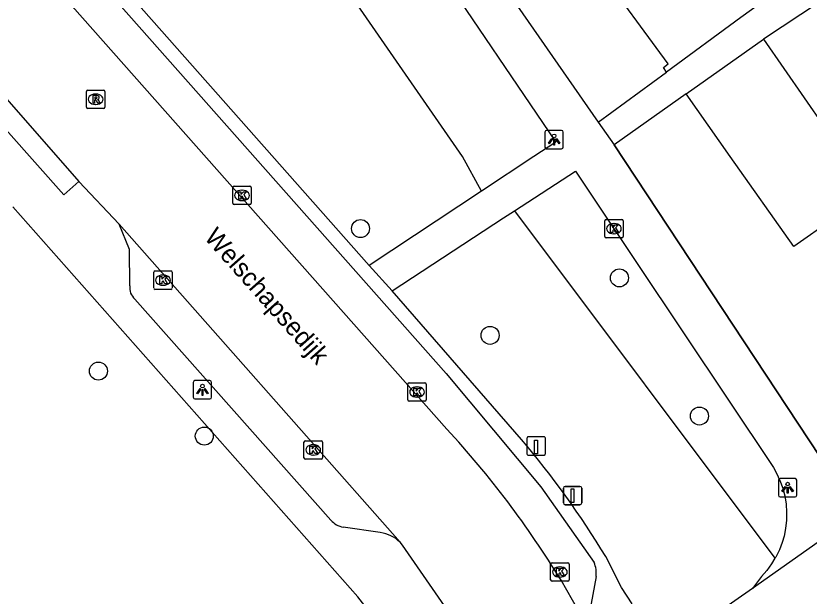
# Model space of a CAD drawing. Extents: x 157466 to 158888, y 383063 to 384677.
# Drawn here: x 157968.71 to 158011.77, y 383476.12 to 383507.63 of the extents above; entities that cross this region are included whole.
import ezdxf

# ---------------------------------------------------------------- set-up
doc = ezdxf.new("R2010")
doc.units = 0
for name, color, linetype in [('IMGEO_Boom', 7, 'Continuous'), ('IMGEO_Groenvoorziening', 7, 'Continuous'), ('IMGEO_Kolk', 7, 'Continuous'), ('IMGEO_Laadpaal', 7, 'Continuous'), ('IMGEO_Lichtpunt', 7, 'Continuous'), ('IMGEO_Muur', 7, 'Continuous'), ('IMGEO_Openbare_ruimte_label', 7, 'Continuous'), ('IMGEO_Pand', 7, 'Continuous'), ('IMGEO_Rijbaan_lokaal_gesloten', 7, 'Continuous'), ('IMGEO_Rioolput', 7, 'Continuous'), ('IMGEO_Verkeersbordpaal', 7, 'Continuous'), ('IMGEO_Voetpad_open', 7, 'Continuous')]:
    doc.layers.add(name, color=color, linetype=linetype)

msp = doc.modelspace()

# ---------------------------------------------------------------- linework, layer by layer
at = {"layer": 'IMGEO_Boom'}
for centre in [(157987.417, 383496.084), (158001.474, 383493.406), (157994.451, 383490.283), (157973.188, 383488.344), (158005.819, 383485.903), (157978.938, 383484.812)]:
    msp.add_circle(centre, 0.489, dxfattribs=at)
at = {"layer": 'IMGEO_Groenvoorziening'}
for points in [[(157993.986, 383498.111), (157992.947, 383500), (157978.989, 383520.199)], [(157995.779, 383497.049), (158009.92, 383478.175)]]:
    msp.add_lwpolyline(points, dxfattribs=at)
at = {"layer": 'IMGEO_Kolk'}
for p, q in [((157980.558, 383498.383), (157981.41, 383498.383)), ((157980.483, 383497.457), (157980.483, 383498.309)), ((157980.971, 383498.163), (157980.996, 383498.163)), ((157981.484, 383498.309), (157981.484, 383497.457)), ((157980.994, 383497.603), (157980.969, 383497.603)), ((157981.41, 383497.383), (157980.558, 383497.383)), ((158000.675, 383495.651), (158000.675, 383496.503)), ((158000.75, 383496.577), (158001.602, 383496.577)), ((158001.163, 383496.357), (158001.188, 383496.357)), ((158001.676, 383496.503), (158001.676, 383495.651)), ((158001.186, 383495.797), (158001.161, 383495.797)), ((158001.602, 383495.577), (158000.75, 383495.577)), ((157976.196, 383492.855), (157976.196, 383493.707)), ((157976.271, 383493.781), (157977.123, 383493.781)), ((157977.197, 383493.707), (157977.197, 383492.855)), ((157976.684, 383493.561), (157976.709, 383493.561)), ((157977.123, 383492.781), (157976.271, 383492.781)), ((157976.707, 383493.001), (157976.682, 383493.001)), ((157989.987, 383486.781), (157989.987, 383487.633)), ((157990.062, 383487.707), (157990.914, 383487.707)), ((157990.988, 383487.633), (157990.988, 383486.781)), ((157990.475, 383487.487), (157990.5, 383487.487)), ((157990.498, 383486.927), (157990.473, 383486.927)), ((157990.914, 383486.707), (157990.062, 383486.707)), ((157984.423, 383484.564), (157985.275, 383484.564)), ((157984.348, 383483.638), (157984.348, 383484.49)), ((157984.836, 383484.344), (157984.861, 383484.344)), ((157985.349, 383484.49), (157985.349, 383483.638)), ((157984.859, 383483.784), (157984.834, 383483.784)), ((157985.275, 383483.564), (157984.423, 383483.564)), ((157997.74, 383477.007), (157997.74, 383477.859)), ((157997.815, 383477.933), (157998.667, 383477.933)), ((157998.228, 383477.713), (157998.253, 383477.713)), ((157998.741, 383477.859), (157998.741, 383477.007)), ((157998.667, 383476.933), (157997.815, 383476.933)), ((157998.251, 383477.153), (157998.226, 383477.153))]:
    msp.add_line(p, q, dxfattribs=at)
for points in [[(157980.558, 383498.383), (157981.41, 383498.383)], [(157980.483, 383497.457), (157980.483, 383498.309)], [(157980.804, 383498.083), (157980.927, 383498.083), (157980.927, 383497.932), (157981.057, 383498.083), (157981.221, 383498.083), (157981.075, 383497.932), (157981.228, 383497.683), (157981.076, 383497.683), (157980.991, 383497.847), (157980.927, 383497.78), (157980.927, 383497.683), (157980.804, 383497.683), (157980.804, 383498.083)], [(157981.484, 383498.309), (157981.484, 383497.457)], [(157981.41, 383497.383), (157980.558, 383497.383)], [(158000.675, 383495.651), (158000.675, 383496.503)], [(158000.75, 383496.577), (158001.602, 383496.577)], [(158000.996, 383496.277), (158001.119, 383496.277), (158001.119, 383496.126), (158001.249, 383496.277), (158001.413, 383496.277), (158001.267, 383496.126), (158001.42, 383495.877), (158001.268, 383495.877), (158001.183, 383496.041), (158001.119, 383495.974), (158001.119, 383495.877), (158000.996, 383495.877), (158000.996, 383496.277)], [(158001.676, 383496.503), (158001.676, 383495.651)], [(158001.602, 383495.577), (158000.75, 383495.577)], [(157976.196, 383492.855), (157976.196, 383493.707)], [(157976.271, 383493.781), (157977.123, 383493.781)], [(157977.197, 383493.707), (157977.197, 383492.855)], [(157976.517, 383493.481), (157976.64, 383493.481), (157976.64, 383493.33), (157976.77, 383493.481), (157976.934, 383493.481), (157976.788, 383493.33), (157976.941, 383493.081), (157976.789, 383493.081), (157976.704, 383493.245), (157976.64, 383493.178), (157976.64, 383493.081), (157976.517, 383493.081), (157976.517, 383493.481)], [(157977.123, 383492.781), (157976.271, 383492.781)], [(157989.987, 383486.781), (157989.987, 383487.633)], [(157990.062, 383487.707), (157990.914, 383487.707)], [(157990.988, 383487.633), (157990.988, 383486.781)], [(157990.308, 383487.407), (157990.431, 383487.407), (157990.431, 383487.256), (157990.561, 383487.407), (157990.725, 383487.407), (157990.579, 383487.256), (157990.732, 383487.007), (157990.58, 383487.007), (157990.495, 383487.171), (157990.431, 383487.104), (157990.431, 383487.007), (157990.308, 383487.007), (157990.308, 383487.407)], [(157990.914, 383486.707), (157990.062, 383486.707)], [(157984.423, 383484.564), (157985.275, 383484.564)], [(157984.348, 383483.638), (157984.348, 383484.49)], [(157984.669, 383484.264), (157984.792, 383484.264), (157984.792, 383484.113), (157984.922, 383484.264), (157985.086, 383484.264), (157984.94, 383484.113), (157985.093, 383483.864), (157984.941, 383483.864), (157984.856, 383484.028), (157984.792, 383483.961), (157984.792, 383483.864), (157984.669, 383483.864), (157984.669, 383484.264)], [(157985.349, 383484.49), (157985.349, 383483.638)], [(157985.275, 383483.564), (157984.423, 383483.564)], [(157997.74, 383477.007), (157997.74, 383477.859)], [(157997.815, 383477.933), (157998.667, 383477.933)], [(157998.741, 383477.859), (157998.741, 383477.007)], [(157998.061, 383477.633), (157998.184, 383477.633), (157998.184, 383477.482), (157998.314, 383477.633), (157998.478, 383477.633), (157998.332, 383477.482), (157998.485, 383477.233), (157998.333, 383477.233), (157998.248, 383477.397), (157998.184, 383477.33), (157998.184, 383477.233), (157998.061, 383477.233), (157998.061, 383477.633)], [(157998.667, 383476.933), (157997.815, 383476.933)]]:
    msp.add_lwpolyline(points, dxfattribs=at)
for centre, start, end in [((157980.56, 383498.307), 91.552, 178.448), ((157980.56, 383498.307), 91.552, 178.448), ((157981.408, 383498.307), 1.552, 88.448), ((157981.408, 383498.307), 1.552, 88.448), ((157980.56, 383497.459), 181.552, 268.448), ((157980.56, 383497.459), 181.552, 268.448), ((157981.408, 383497.459), 271.552, 358.448), ((157981.408, 383497.459), 271.552, 358.448), ((158000.752, 383496.501), 91.552, 178.448), ((158000.752, 383496.501), 91.552, 178.448), ((158001.6, 383496.501), 1.552, 88.448), ((158001.6, 383496.501), 1.552, 88.448), ((158000.752, 383495.653), 181.552, 268.448), ((158000.752, 383495.653), 181.552, 268.448), ((158001.6, 383495.653), 271.552, 358.448), ((158001.6, 383495.653), 271.552, 358.448), ((157976.273, 383493.705), 91.552, 178.448), ((157976.273, 383493.705), 91.552, 178.448), ((157977.121, 383493.705), 1.552, 88.448), ((157977.121, 383493.705), 1.552, 88.448), ((157976.273, 383492.857), 181.552, 268.448), ((157976.273, 383492.857), 181.552, 268.448), ((157977.121, 383492.857), 271.552, 358.448), ((157977.121, 383492.857), 271.552, 358.448), ((157990.064, 383487.631), 91.552, 178.448), ((157990.064, 383487.631), 91.552, 178.448), ((157990.912, 383487.631), 1.552, 88.448), ((157990.912, 383487.631), 1.552, 88.448), ((157990.064, 383486.783), 181.552, 268.448), ((157990.064, 383486.783), 181.552, 268.448), ((157990.912, 383486.783), 271.552, 358.448), ((157990.912, 383486.783), 271.552, 358.448), ((157984.425, 383484.488), 91.552, 178.448), ((157984.425, 383484.488), 91.552, 178.448), ((157985.273, 383484.488), 1.552, 88.448), ((157985.273, 383484.488), 1.552, 88.448), ((157984.425, 383483.64), 181.552, 268.448), ((157984.425, 383483.64), 181.552, 268.448), ((157985.273, 383483.64), 271.552, 358.448), ((157985.273, 383483.64), 271.552, 358.448), ((157997.817, 383477.857), 91.552, 178.448), ((157997.817, 383477.857), 91.552, 178.448), ((157998.665, 383477.857), 1.552, 88.448), ((157998.665, 383477.857), 1.552, 88.448), ((157997.817, 383477.009), 181.552, 268.448), ((157997.817, 383477.009), 181.552, 268.448), ((157998.665, 383477.009), 271.552, 358.448), ((157998.665, 383477.009), 271.552, 358.448)]:
    msp.add_arc(centre, 0.0765, start, end, dxfattribs=at)
for centre, major_axis, ratio, start_param, end_param in [((157980.97, 383497.883), (-0.387, 0.002), 0.722429, 4.712389, 7.853982), ((157980.995, 383497.883), (-0.39, 0.002), 0.717154, 1.570796, 4.712389), ((158001.162, 383496.077), (-0.387, 0.002), 0.722429, 4.712389, 7.853982), ((158001.187, 383496.077), (-0.39, 0.002), 0.717154, 1.570796, 4.712389), ((157976.683, 383493.281), (-0.387, 0.002), 0.722429, 4.712389, 7.853982), ((157976.708, 383493.281), (-0.39, 0.002), 0.717154, 1.570796, 4.712389), ((157990.474, 383487.207), (-0.387, 0.002), 0.722429, 4.712389, 7.853982), ((157990.499, 383487.207), (-0.39, 0.002), 0.717154, 1.570796, 4.712389), ((157984.835, 383484.064), (-0.387, 0.002), 0.722429, 4.712389, 7.853982), ((157984.86, 383484.064), (-0.39, 0.002), 0.717154, 1.570796, 4.712389), ((157998.227, 383477.433), (-0.387, 0.002), 0.722429, 4.712389, 7.853982), ((157998.252, 383477.433), (-0.39, 0.002), 0.717154, 1.570796, 4.712389)]:
    msp.add_ellipse(centre, major_axis=major_axis, ratio=ratio, start_param=start_param, end_param=end_param, dxfattribs=at)
at = {"layer": 'IMGEO_Laadpaal'}
for p, q in [((157996.454, 383484.691), (157996.454, 383483.85)), ((157996.454, 383484.691), (157996.454, 383483.85)), ((157997.37, 383484.775), (157996.529, 383484.775)), ((157997.37, 383484.775), (157996.529, 383484.775)), ((157997.454, 383483.859), (157997.454, 383484.7)), ((157997.454, 383483.859), (157997.454, 383484.7)), ((157996.538, 383483.775), (157997.379, 383483.775)), ((157996.538, 383483.775), (157997.379, 383483.775))]:
    msp.add_line(p, q, dxfattribs=at)
msp.add_lwpolyline([(157996.869, 383484.588), (157997.029, 383484.588), (157997.029, 383483.855), (157996.869, 383483.855), (157996.869, 383484.588)], dxfattribs=at)
for centre, start, end in [((157996.532, 383484.697), 92.4484, 184.2845), ((157996.532, 383484.697), 92.4484, 184.2845), ((157997.376, 383484.697), 2.4484, 94.2845), ((157997.376, 383484.697), 2.4484, 94.2845), ((157996.532, 383483.853), 182.4484, 274.2845), ((157996.532, 383483.853), 182.4484, 274.2845), ((157997.376, 383483.853), 272.4484, 4.2845), ((157997.376, 383483.853), 272.4484, 4.2845)]:
    msp.add_arc(centre, 0.0779, start, end, dxfattribs=at)
at = {"layer": 'IMGEO_Lichtpunt'}
for p, q in [((157998.331, 383501.411), (157997.523, 383501.411)), ((157998.331, 383501.411), (157997.523, 383501.411)), ((157997.429, 383501.316), (157997.429, 383500.509)), ((157997.429, 383501.316), (157997.429, 383500.509)), ((157998.425, 383500.509), (157998.425, 383501.316)), ((157998.425, 383500.509), (157998.425, 383501.316)), ((157997.523, 383500.415), (157998.331, 383500.415)), ((157997.523, 383500.415), (157998.331, 383500.415)), ((157978.338, 383487.732), (157978.338, 383486.925)), ((157978.338, 383487.732), (157978.338, 383486.925)), ((157979.24, 383487.827), (157978.432, 383487.827)), ((157979.24, 383487.827), (157978.432, 383487.827)), ((157979.334, 383486.925), (157979.334, 383487.732)), ((157979.334, 383486.925), (157979.334, 383487.732)), ((157978.432, 383486.831), (157979.24, 383486.831)), ((157978.432, 383486.831), (157979.24, 383486.831)), ((158010.107, 383482.413), (158010.107, 383481.606)), ((158010.107, 383482.413), (158010.107, 383481.606)), ((158011.009, 383482.508), (158010.201, 383482.508)), ((158011.009, 383482.508), (158010.201, 383482.508)), ((158011.103, 383481.606), (158011.103, 383482.413)), ((158011.103, 383481.606), (158011.103, 383482.413)), ((158010.201, 383481.512), (158011.009, 383481.512)), ((158010.201, 383481.512), (158011.009, 383481.512))]:
    msp.add_line(p, q, dxfattribs=at)
for points in [[(157997.803, 383500.98), (157997.842, 383500.952), (157997.654, 383500.69), (157997.616, 383500.717), (157997.803, 383500.98)], [(157997.905, 383500.932), (157997.952, 383500.932), (157997.952, 383500.61), (157997.905, 383500.61), (157997.905, 383500.932)], [(157998.015, 383500.952), (157998.053, 383500.979), (157998.24, 383500.717), (157998.201, 383500.689), (157998.015, 383500.952)], [(157978.712, 383487.396), (157978.751, 383487.368), (157978.563, 383487.106), (157978.525, 383487.133), (157978.712, 383487.396)], [(157978.814, 383487.348), (157978.861, 383487.348), (157978.861, 383487.026), (157978.814, 383487.026), (157978.814, 383487.348)], [(157978.924, 383487.368), (157978.962, 383487.395), (157979.149, 383487.133), (157979.11, 383487.105), (157978.924, 383487.368)], [(158010.481, 383482.077), (158010.52, 383482.049), (158010.332, 383481.787), (158010.294, 383481.814), (158010.481, 383482.077)], [(158010.583, 383482.029), (158010.63, 383482.029), (158010.63, 383481.707), (158010.583, 383481.707), (158010.583, 383482.029)], [(158010.693, 383482.049), (158010.731, 383482.076), (158010.918, 383481.814), (158010.879, 383481.786), (158010.693, 383482.049)]]:
    msp.add_lwpolyline(points, dxfattribs=at)
for centre in [(157997.928, 383501.114), (157978.837, 383487.53), (158010.606, 383482.211)]:
    msp.add_circle(centre, 0.0994, dxfattribs=at)
for centre, start, end in [((157997.523, 383501.316), 90, 180), ((157997.523, 383501.316), 90, 180), ((157998.331, 383501.316), 0, 90), ((157998.331, 383501.316), 0, 90), ((157997.523, 383500.509), 180, 270), ((157997.523, 383500.509), 180, 270), ((157998.331, 383500.509), 270, 0), ((157998.331, 383500.509), 270, 360), ((157978.432, 383487.732), 90, 180), ((157978.432, 383487.732), 90, 180), ((157979.24, 383487.732), 0, 90), ((157979.24, 383487.732), 0, 90), ((157978.432, 383486.925), 180, 270), ((157978.432, 383486.925), 180, 270), ((157979.24, 383486.925), 270, 0), ((157979.24, 383486.925), 270, 360), ((158010.201, 383482.413), 90, 180), ((158010.201, 383482.413), 90, 180), ((158011.009, 383482.413), 0, 90), ((158011.009, 383482.413), 0, 90), ((158010.201, 383481.606), 180, 270), ((158010.201, 383481.606), 180, 270), ((158011.009, 383481.606), 270, 0), ((158011.009, 383481.606), 270, 360)]:
    msp.add_arc(centre, 0.0946, start, end, dxfattribs=at)
at = {"layer": 'IMGEO_Muur'}
msp.add_lwpolyline([(158012.356, 383483.697), (158001.189, 383500.638)], dxfattribs=at)
at = {"layer": 'IMGEO_Pand'}
for points in [[(158004.038, 383504.58), (158003.858, 383504.825), (158004.127, 383505.022), (158000.257, 383510.302), (158000, 383510.114), (157999.919, 383510.224)], [(158010.049, 383508.984), (158008.072, 383507.536), (158004.038, 383504.58)], [(158005.096, 383503.397), (158009.303, 383506.368)], [(158009.303, 383506.368), (158013.717, 383500), (158014.744, 383498.519)], [(158013.051, 383496.601), (158010.946, 383495.114), (158007.495, 383500), (158005.096, 383503.397)]]:
    msp.add_lwpolyline(points, dxfattribs=at)
at = {"layer": 'IMGEO_Rijbaan_lokaal_gesloten'}
for points in [[(157992.101, 383485.193), (157928.672, 383556.808)], [(157967.568, 383503.839), (157972.124, 383498.643)], [(157974.313, 383496.315), (157972.124, 383498.643)], [(157974.313, 383496.315), (157989.562, 383479.045)], [(157994.947, 383470.721), (157993.279, 383473.713), (157989.701, 383478.888), (157989.562, 383479.045)], [(158000.16, 383473.727), (157998.304, 383476.981)]]:
    msp.add_lwpolyline(points, dxfattribs=at)
msp.add_arc((157954.263, 383450.163), 51.563, 31.3385, 42.7932, dxfattribs=at)
at = {"layer": 'IMGEO_Rioolput'}
for p, q in [((157972.54, 383502.68), (157972.54, 383503.532)), ((157972.615, 383503.606), (157973.467, 383503.606)), ((157973.541, 383503.532), (157973.541, 383502.68)), ((157973.028, 383503.386), (157973.053, 383503.386)), ((157973.051, 383502.826), (157973.026, 383502.826)), ((157973.467, 383502.606), (157972.615, 383502.606))]:
    msp.add_line(p, q, dxfattribs=at)
for points in [[(157972.54, 383502.68), (157972.54, 383503.532)], [(157972.615, 383503.606), (157973.467, 383503.606)], [(157973.541, 383503.532), (157973.541, 383502.68)], [(157973.129, 383503.304), (157972.877, 383503.306), (157972.877, 383502.906)], [(157973.055, 383503.225), (157973.001, 383503.225), (157973.001, 383503.144)], [(157973.001, 383503.144), (157973.053, 383503.144)], [(157972.877, 383502.906), (157973.001, 383502.906), (157973.001, 383503.068), (157973.012, 383503.068)], [(157973.059, 383503.039), (157973.13, 383502.906), (157973.27, 383502.906), (157973.205, 383503.032)], [(157973.467, 383502.606), (157972.615, 383502.606)]]:
    msp.add_lwpolyline(points, dxfattribs=at)
for centre, radius, start, end in [((157972.617, 383503.53), 0.0765, 91.552, 178.448), ((157972.617, 383503.53), 0.0765, 91.552, 178.448), ((157973.465, 383503.53), 0.0765, 1.552, 88.448), ((157973.465, 383503.53), 0.0765, 1.552, 88.448), ((157973.037, 383503.333), 0.19, 274.7715, 282.9687), ((157973.061, 383503.129), 0.0964, 77.0061, 93.1865), ((157973.075, 383503.186), 0.0378, 276.6634, 79.6772), ((157973.128, 383503.194), 0.109, 350.3612, 89.416), ((157973.126, 383503.194), 0.112, 277.5842, 350.9817), ((157973.11, 383502.979), 0.108, 29.5134, 73.7905), ((157972.617, 383502.682), 0.0765, 181.552, 268.448), ((157972.617, 383502.682), 0.0765, 181.552, 268.448), ((157973.011, 383503.015), 0.0533, 26.0293, 88.6989), ((157973.465, 383502.682), 0.0765, 271.552, 358.448), ((157973.465, 383502.682), 0.0765, 271.552, 358.448)]:
    msp.add_arc(centre, radius, start, end, dxfattribs=at)
for centre, major_axis, ratio, start_param, end_param in [((157973.027, 383503.106), (-0.387, 0.002), 0.722429, 4.712389, 7.853982), ((157973.052, 383503.106), (-0.39, 0.002), 0.717154, 1.570796, 4.712389)]:
    msp.add_ellipse(centre, major_axis=major_axis, ratio=ratio, start_param=start_param, end_param=end_param, dxfattribs=at)
at = {"layer": 'IMGEO_Verkeersbordpaal'}
for p, q in [((157998.435, 383481.181), (157998.435, 383481.981)), ((157998.435, 383481.981), (157998.435, 383481.181)), ((157998.535, 383482.081), (157999.325, 383482.081)), ((157999.325, 383482.081), (157998.535, 383482.081)), ((157999.425, 383481.981), (157999.425, 383481.181)), ((157999.425, 383481.181), (157999.425, 383481.981)), ((157999.325, 383481.081), (157998.535, 383481.081)), ((157998.535, 383481.081), (157999.325, 383481.081))]:
    msp.add_line(p, q, dxfattribs=at)
msp.add_lwpolyline([(157998.855, 383481.956), (157999.005, 383481.956), (157999.005, 383481.206), (157998.855, 383481.206), (157998.855, 383481.956)], dxfattribs=at)
for centre, start, end in [((157998.535, 383481.981), 90, 180), ((157998.535, 383481.981), 90, 180), ((157999.325, 383481.981), 0, 90), ((157999.325, 383481.981), 360, 90), ((157998.535, 383481.181), 180, 270), ((157998.535, 383481.181), 180, 270), ((157999.325, 383481.181), 270, 0), ((157999.325, 383481.181), 270, 0)]:
    msp.add_arc(centre, 0.1, start, end, dxfattribs=at)
at = {"layer": 'IMGEO_Voetpad_open'}
for points in [[(157930.01, 383558.3), (157983.378, 383498.016), (157992.065, 383488.205), (157997.202, 383482.054), (158000.095, 383477.951)], [(157984.541, 383524.581), (158000.328, 383501.854)], [(157978.989, 383520.199), (157982.718, 383522.845), (157991.425, 383510.532), (157998.027, 383500.773), (157996.836, 383500), (157993.986, 383498.111)], [(157987.894, 383494.074), (157970.368, 383513.905)], [(158012.33, 383508.373), (158009.303, 383506.368)], [(158000.328, 383501.854), (158004.038, 383504.58)], [(157972.124, 383498.643), (157971.311, 383497.917), (157966.723, 383503.066), (157967.568, 383503.839)], [(158005.096, 383503.397), (158001.189, 383500.638)], [(158000.328, 383501.854), (158001.189, 383500.638)], [(158001.189, 383500.638), (158012.356, 383483.697), (158014.419, 383480.567)], [(157995.779, 383497.049), (157999.09, 383499.198), (158000, 383497.835), (158009.832, 383483.112), (158010.005, 383482.804), (158010.19, 383482.403), (158010.338, 383481.987), (158010.448, 383481.56), (158010.52, 383481.124), (158010.553, 383480.684), (158010.546, 383480.242), (158010.499, 383479.803), (158010.414, 383479.37), (158010.316, 383479.043), (158010.157, 383478.636), (158009.963, 383478.245), (158009.92, 383478.175)], [(157993.986, 383498.111), (157987.894, 383494.074)], [(157987.912, 383475.276), (157987.268, 383476.084), (157968.545, 383497.269)], [(157989.142, 383492.696), (157995.189, 383496.666), (157995.779, 383497.049)], [(157974.893, 383492.976), (157974.869, 383494.947), (157974.313, 383496.315)], [(157989.142, 383492.696), (157987.894, 383494.074)], [(157996.15, 383484.634), (157989.142, 383492.696)], [(157985.803, 383480.253), (157975.168, 383492.253)], [(158014.419, 383480.567), (158008.693, 383476.539)], [(157988.488, 383479.57), (157986.478, 383479.871)], [(158002.173, 383475.705), (158001.595, 383476.585), (158000.729, 383478.273)], [(158009.92, 383478.175), (158009.734, 383477.872), (158009.473, 383477.522), (158009.182, 383477.196), (158008.693, 383476.539)], [(158000.203, 383477.185), (157999.854, 383475.228)], [(158008.693, 383476.539), (158006.601, 383475.068)]]:
    msp.add_lwpolyline(points, dxfattribs=at)
for centre, radius, start, end in [((157975.7, 383492.869), 0.814, 172.4469, 229.2027), ((157958.225, 383452.505), 49.705, 31.2264, 40.2705), ((157986.67, 383480.997), 1.142, 220.6459, 260.3408), ((157988.267, 383477.758), 1.826, 44.8367, 83.062), ((157998.844, 383477.384), 1.374, 351.6714, 24.3793)]:
    msp.add_arc(centre, radius, start, end, dxfattribs=at)

# ---------------------------------------------------------------- texts
at = {"layer": 'IMGEO_Openbare_ruimte_label'}
msp.add_text('Welschapsedijk', height=1, rotation=311.5955, dxfattribs=at).set_placement((157978.887, 383495.567))

doc.saveas('drawing.dxf')
